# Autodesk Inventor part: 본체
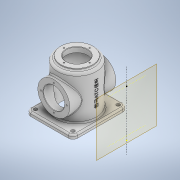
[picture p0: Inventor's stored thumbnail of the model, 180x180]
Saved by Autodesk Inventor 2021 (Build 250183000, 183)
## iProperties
Created: 2021-02
Part Number: 본체
Material: 알루미늄 6061
Document SubType Name: Modeling
Designer: 201-05
Density: 2.7 g/cm^3
Appearance: 기본값
Mass: 1234.94 g
Surface Area: 1072.2 cm^2
Volume: 457.386 cm^3
Author: 201-05
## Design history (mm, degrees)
sketch "스케치1"
  geometry: L1 (60, 70)-(-60, 70); L2 (-60, 70)-(-60, -70); L3 (-60, -70)-(60, -70); L4 (60, -70)-(60, 70); L5 (60, 70)-(-60, -70); L6 (-60, 70)-(60, -70); 1 further point
  constraints: 12 end point, 2 midpoint, 2 parallel, 1 horizontal, 1 perpendicular
  dimensions: "d0" = 120 distance of L3.end L2.end; "d1" = 140 distance of L2.end L1.end
extrude "돌출1" new body sketch "스케치1" distance "d2" = 10; taper "d3" = 0 deg
sketch "스케치2"
  geometry: C1 r 50 at (0, 0); 1 further point
  constraints: 1 centre point, 1 coincident
  dimensions: "d4" = 100 diameter of C1
extrude "돌출2" join sketch "스케치2" distance "d5" = 110; taper "d6" = 0 deg
sketch "스케치3"
  geometry: C1 r 41 at (0, 0); 1 further point
  constraints: 1 centre point, 1 coincident
  dimensions: "d7" = 82 diameter of C1
extrude "돌출3" join sketch "스케치3" distance "d8" = 5; taper "d9" = 0 deg
sketch "스케치4"
  geometry: C1 r 27 at (0, 0); 1 further point
  constraints: 1 centre point, 1 coincident
  dimensions: "d10" = 54 diameter of C1
extrude "돌출4" cut sketch "스케치4" extent not by distance; stored distance "d11" = 100; taper "d12" = 0 deg
sketch "스케치6"
  geometry: C1 r 41 at (0, 60); 1 further point
  constraints: 1 centre point
  dimensions: "d16" = 82 diameter of C1; "d67" = 60 distance of point (0, 0) C1.centre
extrude "돌출6" join sketch "스케치6" stored distance "d17" = 118; taper "d18" = 0 deg
sketch "스케치7"
  geometry: C1 r 27 at (0, 0); 1 further point
  constraints: 1 centre point
  dimensions: "d19" = 54 diameter of C1
extrude "돌출7" cut sketch "스케치7" extent not by distance; stored distance "d20" = 0; taper "d21" = 0 deg
sketch "스케치5"
  geometry: C1 r 42 at (0, 0); 1 further point
  constraints: 1 centre point, 1 coincident
  dimensions: "d13" = 84 diameter of C1
extrude "돌출5" cut sketch "스케치5" distance "d14" = 112; taper "d15" = 0 deg
sketch "스케치8"
  geometry: A1 r 33 centre (0, 0) between (-33, 0) and (0, 33); 3 further points
  constraints: 4 point on circle, 2 horizontal alignment, 2 vertical alignment, 1 centre point, 1 coincident
  dimensions: "d22" = 66 diameter of A1
hole "구멍1" sketch "스케치8" at (-33, 0), (0, 33), (33, 0), (0, -33) diameter "d23" = 3.242; stored, may be unused: countersink angle "d27" = 90 deg, drill point angle "d29" = 118 deg; dims "d24" = 8, "d25" = 4, "d26" = 2, "d28" = 10
sketch "스케치9"
  geometry: L1 (0, -75.803)-(0, 75.803); L2 (-57.676, 0)-(60.972, 0); C1 r 27 at (0, 0) reference; A1 r 33 centre (0, 0) between (0, 33) and (-33, 0); 4 further points
  constraints: 4 end point, 4 point on circle, 2 horizontal alignment, 2 midpoint, 2 point on line, 2 vertical alignment, 1 centre point, 1 coincident, 1 horizontal, 1 vertical
  dimensions: "d30" = 66 diameter of A1
hole "구멍2" sketch "스케치9" at (0, 33), (-33, 0), (0, -33), (33, 0) diameter "d31" = 3.242; stored, may be unused: countersink angle "d35" = 90 deg, drill point angle "d37" = 118 deg; dims "d32" = 8, "d33" = 4, "d34" = 2, "d36" = 10
sketch "스케치10"
  geometry: L1 (60, 70)-(-60, 70) reference; L2 (60, -70)-(60, 70) reference; L3 (-60, 70)-(-60, -70) reference; L4 (-60, -70)-(60, -70) reference; C1 r 4.5 at (48, 58); C2 r 4.5 at (48, -58); C3 r 4.5 at (-48, -58); C4 r 4.5 at (-48, 58); 1 further point
  constraints: 4 centre point, 2 horizontal alignment, 2 vertical alignment
  dimensions: "d38" = 9 diameter of C1; "d39" = 9 diameter of C2; "d40" = 9 diameter of C3; "d41" = 9 diameter of C4; "d42" = 12 distance from line of L1 C1.centre; "d43" = 12 distance from line of L2 C1.centre; "d44" = 12 distance from line of L3 C3.centre; "d45" = 12 distance from line of L4 C3.centre
extrude "돌출8" cut sketch "스케치10" extent not by distance; stored distance "d46" = 0; taper "d47" = 0 deg
node "작업 평면2"
sketch "스케치12"
  geometry: L1 (120, -50)-(120, 50) reference; L2 (10, 50)-(10, -50) reference; L3 (163.739, 0)-(-33.956, 0); 2 further points
  constraints: 2 end point, 1 horizontal, 1 midpoint, 1 point on line
sketch "스케치11"
  geometry: L1 (163.739, 0)-(-33.956, 0) reference; 3 further points
  constraints: 1 horizontal alignment, 1 midpoint, 1 other
  dimensions: "d50" = 66 distance of point (0, 0) point (66, 0)
feature "엠보싱1" sketch "스케치11" dims "d0" = 120, "d1" = 140, "d10" = 54, "d51" = 0.5, "d52" = 0
fillet "모깎기7" dims "d65" = 12
fillet "모깎기3" dims "d55" = 3
fillet "모깎기4" dims "d56" = 6
fillet "모깎기5" dims "d57" = 3
chamfer "모따기1" distance "d58" = 1; stored, may be unused: second distance "d59" = 2, angle "d60" = 45 deg
fillet "모깎기6" dims "d61" = 3
chamfer "모따기2" distance "d62" = 1; stored, may be unused: second distance "d63" = 2, angle "d64" = 45 deg
fillet "모깎기8" dims "d66" = 4
node "솔리드1"
mirror "미러1"
feature "A9D066F2-1C7D-4E18-AEED-F7BC21143FA4" dims "d23" = 3.242, "d24" = 8, "d25" = 4, "d26" = 2, "d27" = 90 deg, "d28" = 10, "d29" = 118 deg
other parameters: "d49" = 127.5
